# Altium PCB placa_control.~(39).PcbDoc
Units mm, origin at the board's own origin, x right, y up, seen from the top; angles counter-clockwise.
Board outline 57.05 x 111.17 mm, 2 copper layers (Top Layer, Bottom Layer); 31 components, 24 nets, 126 pads, 98 vias.
Unrouted connection lines stored in the file: 20.
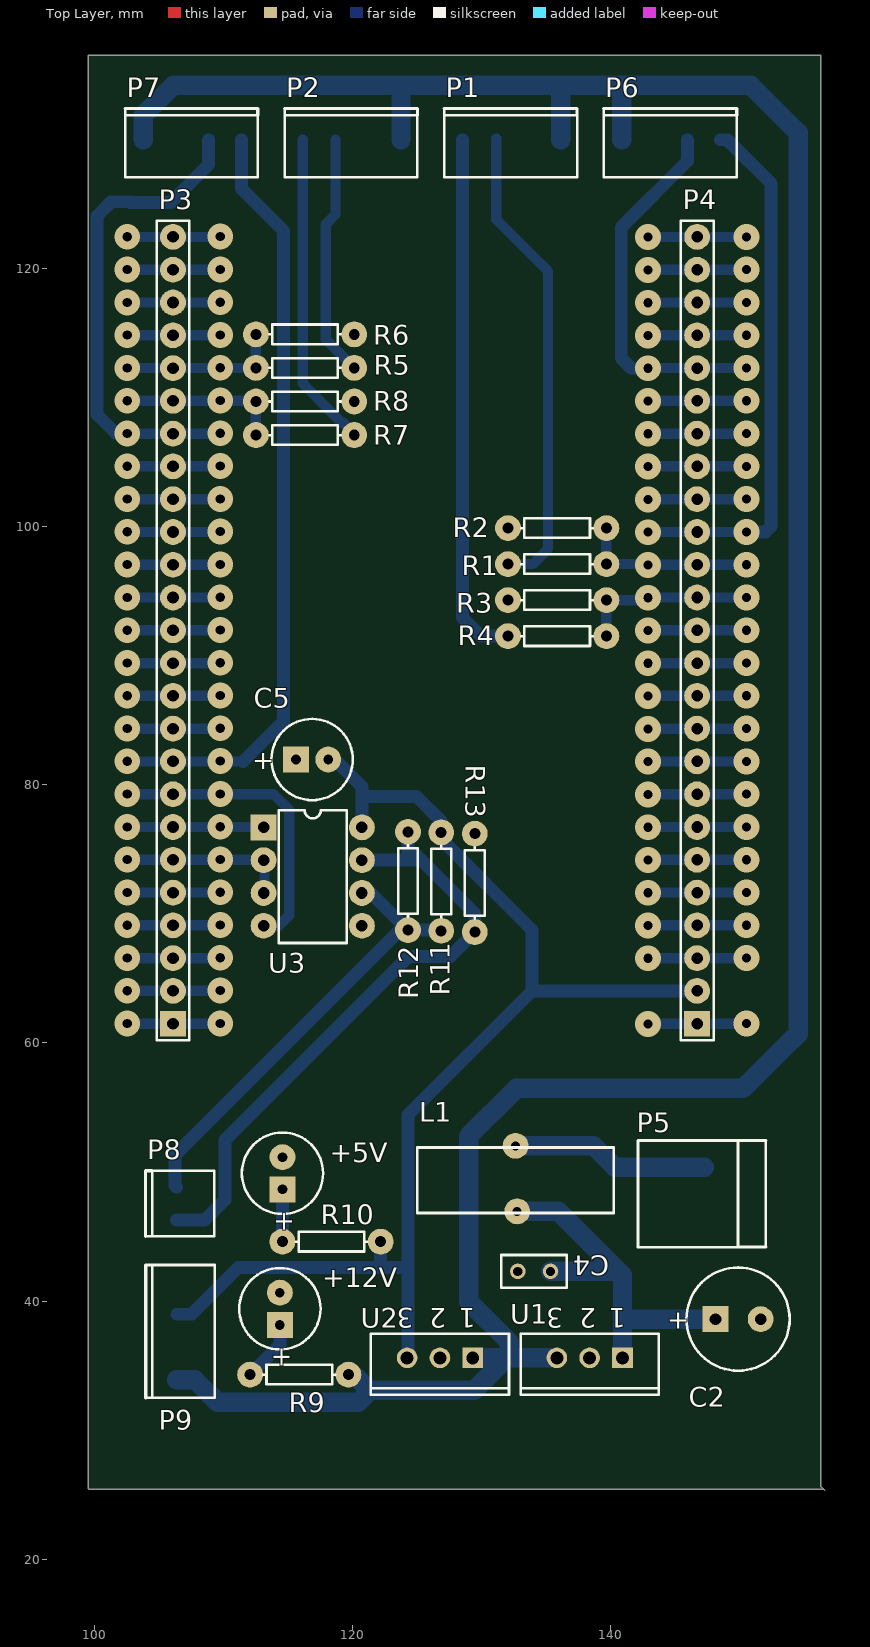
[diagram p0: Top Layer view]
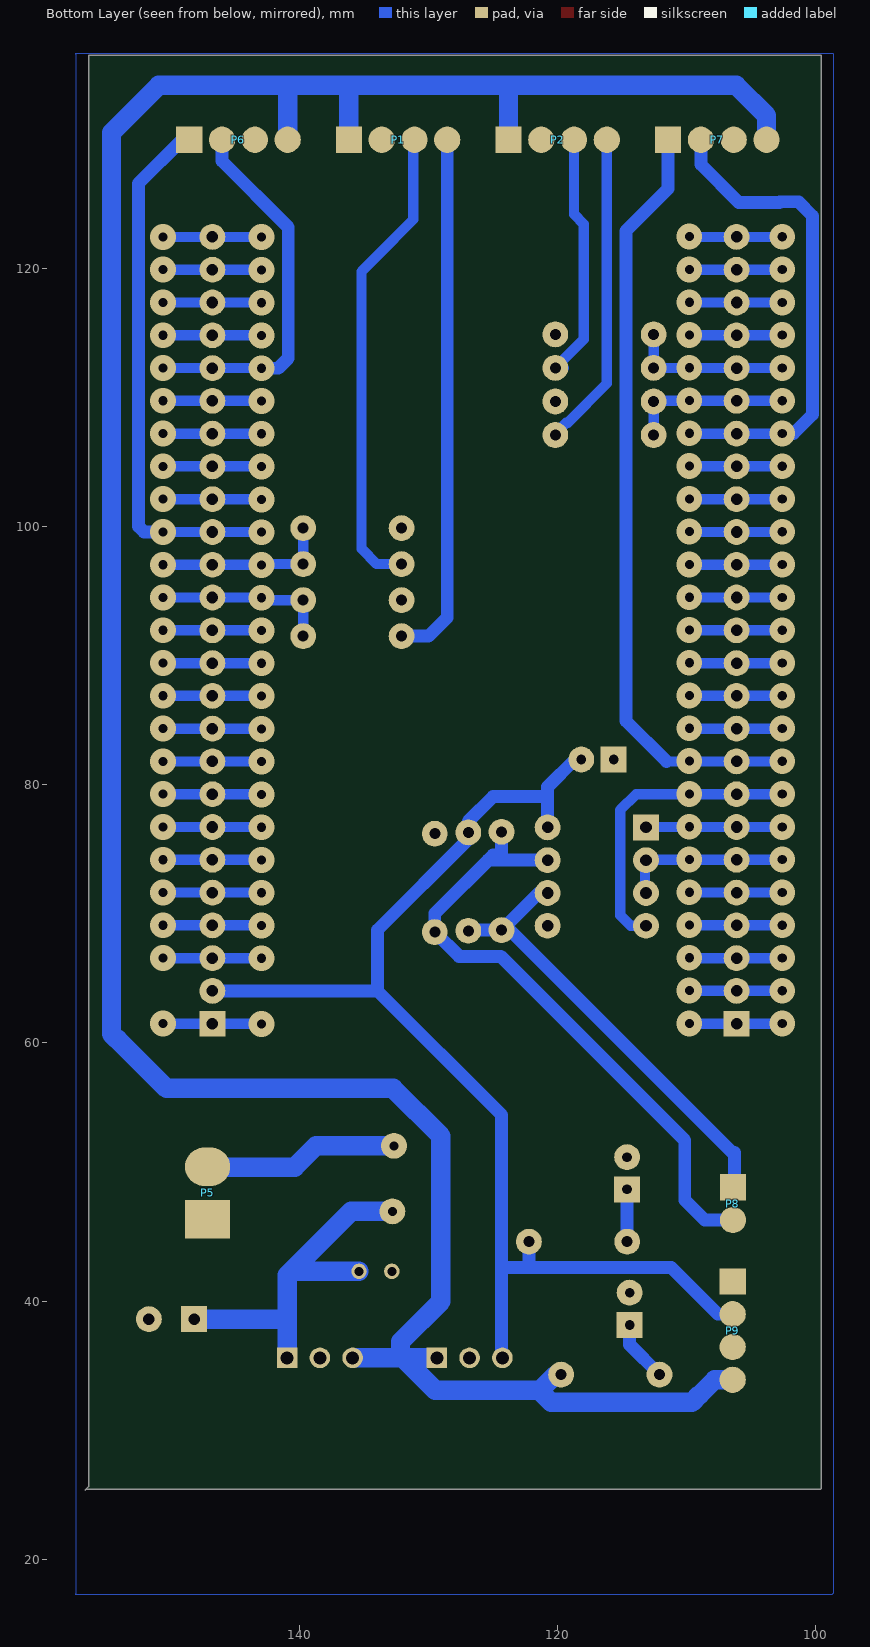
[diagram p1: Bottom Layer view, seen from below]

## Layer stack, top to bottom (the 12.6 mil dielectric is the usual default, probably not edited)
Top Layer: signal copper 0.0356
Dielectric: dielectric 0.32, FR-4, Dk 4.8
Bottom Layer: signal copper 0.0356

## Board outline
99.575,25.45 99.625,25.4 156.55,25.4 156.6,25.35 156.325,25.625 156.325,136.525 99.55,136.525 99.55,25.475

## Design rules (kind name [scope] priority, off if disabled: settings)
Clearance [All] p1: gap=0.4
ComponentClearance [All] p1: gap=0.254 collisioncheckmode=2 verticalgap=0.254
PlaneConnect [All] p1: planeconnectstyle=Direct reliefexpansion=0.508 reliefentries=4 reliefconductorwidth=0.6 reliefairgap=0.254
PolygonConnect [All] p1: connectstyle=Direct reliefconductorwidth=0.6 reliefentries=4 polygonreliefangle="90 Angle"
RoomDefinition REGULADOR [InComponentClass('REGULADOR')] p1: confinementstyle=ConfineIn formatcopy=TRUE lockcomponents=FALSE outline 99.475,32.15 155.025,32.15 155.025,55.55 99.475,55.55
RoomDefinition INTERFAZ [InComponentClass('INTERFAZ')] p2: confinementstyle=ConfineIn formatcopy=TRUE lockcomponents=FALSE outline 110.775,62.675 143.675,62.675 143.675,88.075 110.775,88.075
RoomDefinition ENCODER [InComponentClass('ENCODER')] p3: confinementstyle=ConfineOut formatcopy=TRUE lockcomponents=FALSE outline 141.4,147.25 141.4,152.45 116,152.45 116,147.25
RoomDefinition BOARD-ARM [InComponentClass('BOARD-ARM')] p4: confinementstyle=ConfineOut formatcopy=TRUE lockcomponents=FALSE outline 166.025,120.7 232.827,120.7 232.827,146.1 166.025,146.1
RoomDefinition placa_control_esquema [InComponentClass('placa_control_esquema')] p5: confinementstyle=ConfineIn formatcopy=TRUE lockcomponents=FALSE outline 98.175,30.55 156.55,30.55 156.55,136.6 98.175,136.6
RoutingVias [All] p1: holewidth=0.711 width=2 viastyle="Through Hole" minholewidth=0.711 minwidth=1.27 maxholewidth=0.711 maxwidth=2
SolderMaskExpansion [All] p1: expansion=0.102
TestPointUsage [All] p1: valid=0 allowmultiple=FALSE
Testpoint [All] p1: side=15 testpointundercomponent=TRUE minsize=1.016 maxsize=2.54 preferedsize=1.524 minholesize=0 maxholesize=1.016 preferedholesize=0.813 testpointgrid=0.025 style=1023 order=0123456789
Width [All] p1: maxlimit=1.5 minlimit=0.8 preferedwidth=0.8
17 further rules are at their usual default settings.

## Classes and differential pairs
component class placa_control_esquema: P6 P7 P9
component class REGULADOR: +5V +12V C2 C4 L1 P5 R9 R10 U1 U2
component class BOARD-ARM: P3 P4
component class ENCODER: P1 P2 R1 R2 R3 R4 R5 R6 R7 R8
component class INTERFAZ: C5 P8 R11 R12 R13 U3

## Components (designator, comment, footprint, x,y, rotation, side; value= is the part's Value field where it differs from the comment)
+5V "LED2" CAPPR2.5-6.3X5 114.6,49.9 r90 top (schematic designator VCC2)
+12V "LED2" CAPPR2.5-6.3X5 114.4,39.4 r90 top (schematic designator VCC1)
C2 "Cap Pol3" CAPPR3.5-8X15 149.9,38.6 r0 top
C4 "Cap" RAD-0.1 134.1,42.3 r0 top
C5 "Cap" CAPPR2.5-6.3X5 116.894,81.958 r0 top
L1 "Inductor Iron" bobina_Choque 135.2,51.9 r180 top
P1 "Header 4" HDR1X5 128.533,137.6 r180 top
P2 "Header 4" HDR1X5 116.167,137.6 r180 top
P3 "Header 25" HDR1X25 106.115,61.49 r90 top
P4 "Header 25" HDR1X25 146.73,61.49 r90 top
P5 "Header 2" pwheader1x2 147.1,48.5 r90 top
P6 "Header 4" HDR1X5 140.9,137.6 r180 top
P7 "Header 4" HDR1X5 103.8,137.6 r180 top
P8 "Header 2" wf2s 106.4,41.2 r270 top
P9 "Header 4" HDR1X5 98.8,33.9 r270 top
R1 "metal film 2%" AXIAL-0.3 135.884,97.102 r180 top
R2 "metal film 2%" AXIAL-0.3 135.884,99.894 r0 top
R3 "metal film 2%" AXIAL-0.3 135.884,91.518 r180 top
R4 "metal film 2%" AXIAL-0.3 135.884,94.31 r0 top
R5 "metal film 2%" AXIAL-0.3 116.35,112.3 r0 top
R6 "metal film 2%" AXIAL-0.3 116.35,114.9 r180 top
R7 "metal film 2%" AXIAL-0.3 116.35,107.1 r0 top
R8 "metal film 2%" AXIAL-0.3 116.35,109.7 r180 top
R9 "Carbon 1/8w 5%" AXIAL-0.3 115.9,34.3 r0 top
R10 "Carbon 1/8w 5%" AXIAL-0.3 118.4,44.6 r0 top
R11 "Carbon 1/8w 5%" AXIAL-0.3 126.9,72.5 r90 top
R12 "Carbon 1/8w 5%" AXIAL-0.3 124.326,72.55 r270 top
R13 "Carbon 1/8w 5%" AXIAL-0.3 129.5,72.4 r270 top
U1 "LM78L12ACZ" T03B 138.4,35.6 r180 top
U2 "LM78L05ACZ" T03B 126.8,35.6 r180 top
U3 "SN75176BP" 626-05 116.944,72.89 r270 top

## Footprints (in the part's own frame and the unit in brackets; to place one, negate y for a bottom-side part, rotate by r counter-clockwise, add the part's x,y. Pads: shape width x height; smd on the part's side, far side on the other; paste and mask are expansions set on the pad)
626-05 [mm] "DIP; 8 Leads; Row Spacing 7.62 mm; Pitch 2.54 mm"
  rect 2x2 hole 0.9: 1(-3.81,-3.81)
  round 2 hole 0.9: 2(-1.27,-3.81) 3(1.27,-3.81) 4(3.81,-3.81) 5(3.81,3.81) 6(1.27,3.81) 7(-1.27,3.81) 8(-3.81,3.81)
  silkscreen extent -5.15,-2.65 5.15,2.65
AXIAL-0.3 [mm] "Resistor; 2 Leads"
  round 2 hole 0.85: 1(-3.81,0) 2(3.81,0)
  silkscreen extent -2.77,-0.76 2.77,0.76
bobina_Choque [mm]
  round 2 hole 0.7: 1(2.54,-0.127) 2(2.413,4.953)
  silkscreen extent -5.08,0 10.16,5.08
CAPPR2.5-6.3X5 [mm] "Capacitor, Electrolytic, Radial; Body 6.3 x 5 mm (Dia.xH typ); Pin Spacing 2.5 mm (typ)"
  rect 2x2 hole 0.75: 1(-1.25,0)
  round 2 hole 0.75: 2(1.25,0)
  silkscreen extent -3.15,-3.15 3.15,3.15
CAPPR3.5-8X15 [mm] "Capacitor, Electrolytic, Radial; Body 8 x 15 mm (Dia.xH typ); Pin Spacing 3.5 mm (typ)"
  rect 2x2 hole 0.9: 1(-1.75,0)
  round 2 hole 0.9: 2(1.75,0)
  silkscreen extent -4,-4 4,4
HDR1X5 [mil]
  rect 80x80 smd far side: 1(-300,300)
  round 80 smd far side: 2(-200,300) 3(-100,300) 4(0,300)
  silkscreen extent -350,205 55,415
HDR1X25 [mm] "Connector; Header; 25 Position"
  rect 2x2 hole 0.9: 1(0,0)
  round 2 hole 0.9: 2(2.54,0) 3(5.08,0) 4(7.62,0) 5(10.16,0) 6(12.7,0) 7(15.24,0) 8(17.78,0) 9(20.32,0) 10(22.86,0) 11(25.4,0) 12(27.94,0) 13(30.48,0) 14(33.02,0) 15(35.56,0) 16(38.1,0) 17(40.64,0) 18(43.18,0) 19(45.72,0) 20(48.26,0) 21(50.8,0) 22(53.34,0) 23(55.88,0) 24(58.42,0) 25(60.96,0)
  silkscreen extent -1.27,-1.27 62.23,1.27
pwheader1x2 [mm]
  rect 3x3.5 smd far side: 1(-2.159,0)
  oval 3x3.5 smd far side: 2(1.905,0)
  silkscreen extent -4.32,-4.95 3.94,4.95
RAD-0.1 [mm] "Indicating Instrument; 2 Leads"
  round 1.2 hole 0.7: 1(-1.27,0) 2(1.27,0)
  silkscreen extent -2.54,-1.27 2.54,1.27
T03B [mm] "TO, Thru-Hole, Vertical, Heatsink Mounted; 3 In-Line Leads; Pitch 2.54 mm"
  rect 1.6x1.6 hole 1: 1(-2.54,0)
  round 1.6 hole 1: 2(0,0) 3(2.54,0)
  silkscreen extent -5.35,-1.85 5.35,2.85
wf2s [mil]
  rect 80x80 smd far side: 1(-300,0)
  round 80 smd far side: 2(-200,0)
  silkscreen extent -350,-95 -150,115

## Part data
+5V +12V: "Typical RED, GREEN, YELLOW, AMBER GaAs LED"
C2: "Polarized Capacitor 35V"
C4 C5: "Capacitor"
L1: "Magnetic-Core Inductor"
P1 P2 P6 P7 P9: "Header, 4-Pin"
P3 P4: "Header, 25-Pin"
P5 P8: "Header, 2-Pin"
R1 R2 R3 R4 R5 R6 R7 R8 R9 R10 R11 R12 R13: library part "Res Semi", "Semiconductor Resistor"
U1 U2: "3-Terminal Positive Regulator"
U3: "Differential Bus Transceiver"

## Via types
v1: diameter 2, hole 0.711, Top Layer to Bottom Layer, 98 vias

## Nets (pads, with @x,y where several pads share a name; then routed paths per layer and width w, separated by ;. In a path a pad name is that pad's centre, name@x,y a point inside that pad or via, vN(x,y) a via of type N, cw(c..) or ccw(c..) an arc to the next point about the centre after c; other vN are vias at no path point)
+5V: C5.2 P4.2 P9.2 R10.2 R11.2 U2.3 U3.8 | length 95.2
  Bottom Layer w1: P9.2 107.555,38.98 111.175,42.6 124.25,42.6 124.325,42.525 ; C5.2@118.642,81.958 120.754,79.846 U3.8 U3.8@120.975,76.7 ; 120.754,79.1 124.975,79.1 R11.2@126.9,77.175 ; 122.21,42.615 R10.2 ; U2.3@124.325,35.5 124.325,54.425 133.93,64.03 ; R11.2 126.9,75.775 133.93,68.745 133.93,64.03 ; P4.2 133.93,64.03
+12V: P1.1 P2.1 P6.4 P7.4 P9.4 R9.2 U1.3 U2.1 | length 221.3
  Bottom Layer w1.5: P7.4 103.8,131.85 106.15,134.2 150.875,134.2 154.55,130.525 154.55,60.7 154.125,60.275 154.075,60.275 150.275,56.475 132.725,56.475 129.025,52.775 129.025,39.975 132.15,36.85 132.15,35.6 ; P9.4 107.8,33.9 108.962,32.738 ; 108.975,32.75 109.575,32.15 120.475,32.15 121.425,33.1 ; R9.2@119.65,34.225 120.2,34.225 121.325,33.1 129.475,33.1 131.875,35.5 ; P2.1 123.787,134.112 123.875,134.2 ; U2.1 U1.3 ; P1.1 136.153,134.053 136.3,134.2 ; 140.8,134.2 140.9,134.1 P6.4
GND: +5V.2 +12V.2 C2.2 C4.1 C5.1 P1.2 P2.2 P4.1 P5.1 P6.3 P7.3 P9.1 P9.3 R2.1 R4.1 R6.1 R8.1 R13.1 U1.2 U2.2 U3.5 | length 7.2
  Bottom Layer w0.8: v1@143.23,61.49 v1@150.415,61.49
  other v1: 142.925,61.475 150.55,61.495
IN_SD_1: P4.21 P6.2 | length 28.6
  Bottom Layer w0.8: v1@143.23,112.29 v1@150.415,112.29
  Bottom Layer w1: v1(142.925,112.275) 141.625,112.275 140.85,113.05 140.85,123.2 145.98,128.33 P6.2
  other v1: 150.55,112.295
IN_SD_2: P3.19 P7.2 | length 37.8
  Bottom Layer w0.8: v1@102.615,107.21 v1@109.8,107.21
  Bottom Layer w1: v1(102.575,107.22) 101.705,107.22 100.225,108.7 100.225,124.075 101.325,125.175 102.75,125.175 102.8,125.125 105.95,125.125 108.88,128.055 P7.2
  other v1: 109.775,107.235
NetC2_1: C2.1 C4.2 L1.2 U1.1 | length 29.1
  Bottom Layer w1.5: L1.2 135.978,46.947 140.94,41.985 U1.1 ; C4.2 140.45,42.3 140.6,42.15 ; 140.94,38.5 141.04,38.6 C2.1
NetL1_1: L1.1 P5.2 | length 15.3
  Bottom Layer w1.5: L1.1 138.698,52.027 140.35,50.375 P5.2@147.275,50.375
NetP1_3: P1.3 R1.2 | length 37
  Bottom Layer w0.8: P1.3@131.175,130.05 131.175,123.8 134.05,120.925 134.05,120.9 135.175,119.775 135.175,98.275 134.002,97.102 R1.2
NetP1_4: P1.4 R3.2 | length 41.2
  Bottom Layer w1: P1.4 128.533,92.967 129.982,91.518 R3.2
NetP2_3: P2.3 R5.2 | length 19.6
  Bottom Layer w0.8: P2.3 118.707,124.207 117.948,123.448 117.948,114.512 R5.2 R5.2@119.5,112.3
NetP2_4: P2.4 R7.2 | length 24.7
  Bottom Layer w0.8: P2.4 116.167,111.093 119.204,108.056 119.319,108.056 R7.2@120.325,107.05
NetP3_6: P3.6 U3.2 U3.3 | length 13.3
  Bottom Layer w0.8: v1@102.615,74.19 U3.2@113.21,74.19 ; U3.3 113.21,71.695 U3.2@113.21,74.19 ; U3.2@113.25,74.15 U3.2@113.21,74.19
  other v1: 102.575,74.2 109.775,74.215
NetP3_7: P3.7 U3.1 | length 10.5
  Bottom Layer w0.8: v1@102.615,76.73 U3.1@113.104,76.73
  other v1: 102.575,76.74 109.775,76.755
NetP3_8: P3.8 U3.4 | length 23.5
  Bottom Layer w0.8: v1@102.615,79.27 113.905,79.27 115.125,78.05 115.125,69.9 114.305,69.08 U3.4
  other v1: 102.575,79.28 109.775,79.295
NetP3_20: P3.20 R7.1 R8.2 | length 12.5
  Bottom Layer w0.8: v1@102.615,109.75 112.49,109.75 R8.2 R7.1
  other v1: 102.575,109.76 109.775,109.775
NetP3_21: P3.21 R5.1 R6.2 | length 12.6
  Bottom Layer w0.8: v1@102.615,112.29 112.53,112.29 R5.1@112.5,112.32 ; R5.1 R6.2
  other v1: 102.575,112.3 109.775,112.315
NetP4_14: P4.14 R3.1 R4.2 | length 13
  Bottom Layer w0.8: R3.1 R4.2 v1@142.74,94.31 ; v1@143.23,94.51 v1@150.415,94.51
  other v1: 142.925,94.495 150.55,94.515
NetP4_15: P4.15 R1.1 R2.2 | length 13.1
  Bottom Layer w0.8: R2.2 R1.1 v1@142.858,97.102 ; v1@143.23,97.05 v1@150.415,97.05
  other v1: 142.925,97.035 150.55,97.055
NetP8_1: P8.1 R11.1 R12.2 U3.6 | length 35.5
  Bottom Layer w1: 106.275,51.5 106.275,48.945 P8.1 ; 106.4,51.45 123.95,69 R12.2@124.2,69 ; U3.6 121.446,71.62 R12.2 ; R12.2@124.326,69.126 R12.2 ; R11.1 126.85,68.74 R12.2
NetP8_2: P8.2 R12.1 R13.2 U3.7 | length 50
  Bottom Layer w1: P8.2 108.58,46.28 110.131,47.831 110.131,52.456 124.385,66.71 127.61,66.71 129.5,68.6 129.5,70.025 124.976,74.549 124.326,74.549 R12.1 R12.1@124.366,76.4 ; U3.7 125.365,74.16
NetR9_1: +12V.1 R9.1 | length 4.8
  Bottom Layer w1: R9.1 114.4,36.61 +12V.1
NetR10_1: +5V.1 R10.1 | length 4.2
  Bottom Layer w1: R10.1@114.475,44.525 114.6,44.65 +5V.1
PWM_1: P4.16 P6.1 | length 41.1
  Bottom Layer w0.8: v1@143.23,99.59 v1@150.415,99.59
  Bottom Layer w1: P6.1 149.07,129.98 152.45,126.6 152.45,100.025 152.025,99.6 v1@150.65,99.6
  other v1: 142.925,99.575 150.55,99.595
PWM_2: P3.9 P7.1 | length 59.7
  Bottom Layer w0.8: v1@102.615,81.81 111.535,81.81
  Bottom Layer w1: P7.1 111.42,126.18 114.675,122.925 114.675,84.95 111.535,81.81
  other v1: 102.575,81.82 109.775,81.835
pads on no net: P3.1 P3.2 P3.3 P3.4 P3.5 P3.10 P3.11 P3.12 P3.13 P3.14 P3.15 P3.16 P3.17 P3.18 P3.22 P3.23 P3.24 P3.25 P4.3 P4.4 P4.5 P4.6 P4.7 P4.8 P4.9 P4.10 P4.11 P4.12 P4.13 P4.17 P4.18 P4.19 P4.20 P4.22 P4.23 P4.24 P4.25
copper on no net: | length 265.8
  Bottom Layer w0.8: v1@102.615,61.49 v1@109.8,61.49 ; v1@102.615,64.03 v1@109.8,64.03 ; v1@102.615,66.57 v1@109.8,66.57 ; v1@102.615,69.11 v1@109.8,69.11 ; v1@102.615,71.65 v1@109.8,71.65 ; v1@102.615,84.35 v1@109.8,84.35 ; v1@102.615,86.89 v1@109.8,86.89 ; v1@102.615,89.43 v1@109.8,89.43 ; v1@102.615,91.97 v1@109.8,91.97 ; v1@102.615,94.51 v1@109.8,94.51 ; v1@102.615,97.05 v1@109.8,97.05 ; v1@102.615,99.59 v1@109.8,99.59 ; v1@102.615,102.13 v1@109.8,102.13 ; v1@102.615,104.67 v1@109.8,104.67 ; v1@102.615,114.83 v1@109.8,114.83 ; v1@102.615,117.37 v1@109.8,117.37 ; v1@102.615,119.91 v1@109.8,119.91 ; v1@102.615,122.45 v1@109.8,122.45 ; v1@143.23,66.57 v1@150.415,66.57 ; v1@143.23,69.11 v1@150.415,69.11 ; v1@143.23,71.65 v1@150.415,71.65 ; v1@143.23,74.19 v1@150.415,74.19 ; v1@143.23,76.73 v1@150.415,76.73 ; v1@143.23,79.27 v1@150.415,79.27 ; v1@143.23,81.81 v1@150.415,81.81 ; v1@143.23,84.35 v1@150.415,84.35 ; v1@143.23,86.89 v1@150.415,86.89 ; v1@143.23,89.43 v1@150.415,89.43 ; v1@143.23,91.97 v1@150.415,91.97 ; v1@143.23,102.13 v1@150.415,102.13 ; v1@143.23,104.67 v1@150.415,104.67 ; v1@143.23,107.21 v1@150.415,107.21 ; v1@143.23,109.75 v1@150.415,109.75 ; v1@143.23,114.83 v1@150.415,114.83 ; v1@143.23,117.37 v1@150.415,117.37 ; v1@143.23,119.91 v1@150.415,119.91 ; v1@143.23,122.45 v1@150.415,122.45
  other v1: 102.575,61.5 109.775,61.515 102.575,64.04 109.775,64.055 142.925,66.555 102.575,66.58 150.55,66.575 109.775,66.595 142.925,69.095 102.575,69.12 150.55,69.115 109.775,69.135 142.925,71.635 102.575,71.66 150.55,71.655 109.775,71.675 142.925,74.175 150.55,74.195 142.925,76.715 150.55,76.735 142.925,79.255 150.55,79.275 142.925,81.795 150.55,81.815 142.925,84.335 102.575,84.36 150.55,84.355 109.775,84.375 142.925,86.875 102.575,86.9 150.55,86.895 109.775,86.915 142.925,89.415 102.575,89.44 150.55,89.435 109.775,89.455 142.925,91.955 102.575,91.98 150.55,91.975 109.775,91.995 102.575,94.52 109.775,94.535 102.575,97.06 109.775,97.075 102.575,99.6 109.775,99.615 142.925,102.115 102.575,102.14 150.55,102.135 109.775,102.155 142.925,104.655 102.575,104.68 150.55,104.675 109.775,104.695 142.925,107.195 150.55,107.215 142.925,109.735 150.55,109.755 142.925,114.815 102.575,114.84 150.55,114.835 109.775,114.855 142.925,117.355 102.575,117.38 150.55,117.375 109.775,117.395 142.925,119.895 102.575,119.92 150.55,119.915 109.775,119.935 142.925,122.435 102.575,122.46 150.55,122.455 109.775,122.475

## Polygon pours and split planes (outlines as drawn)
GND on Bottom Layer "plano_señal_fuerte" (solid, remove dead copper, shelved, pour order 1000): 98.575,136.6 98.627,136.65 157.35,136.65 157.324,136.625 157.324,17.3 157.35,17.275 98.704,17.275 98.627,17.35 98.575,17.4

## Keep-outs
Drill Guide:
  rectangle: 103.975,54.175 149.375,124.375

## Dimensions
145.906,143.55 to 105.306,142.325 on Top Layer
